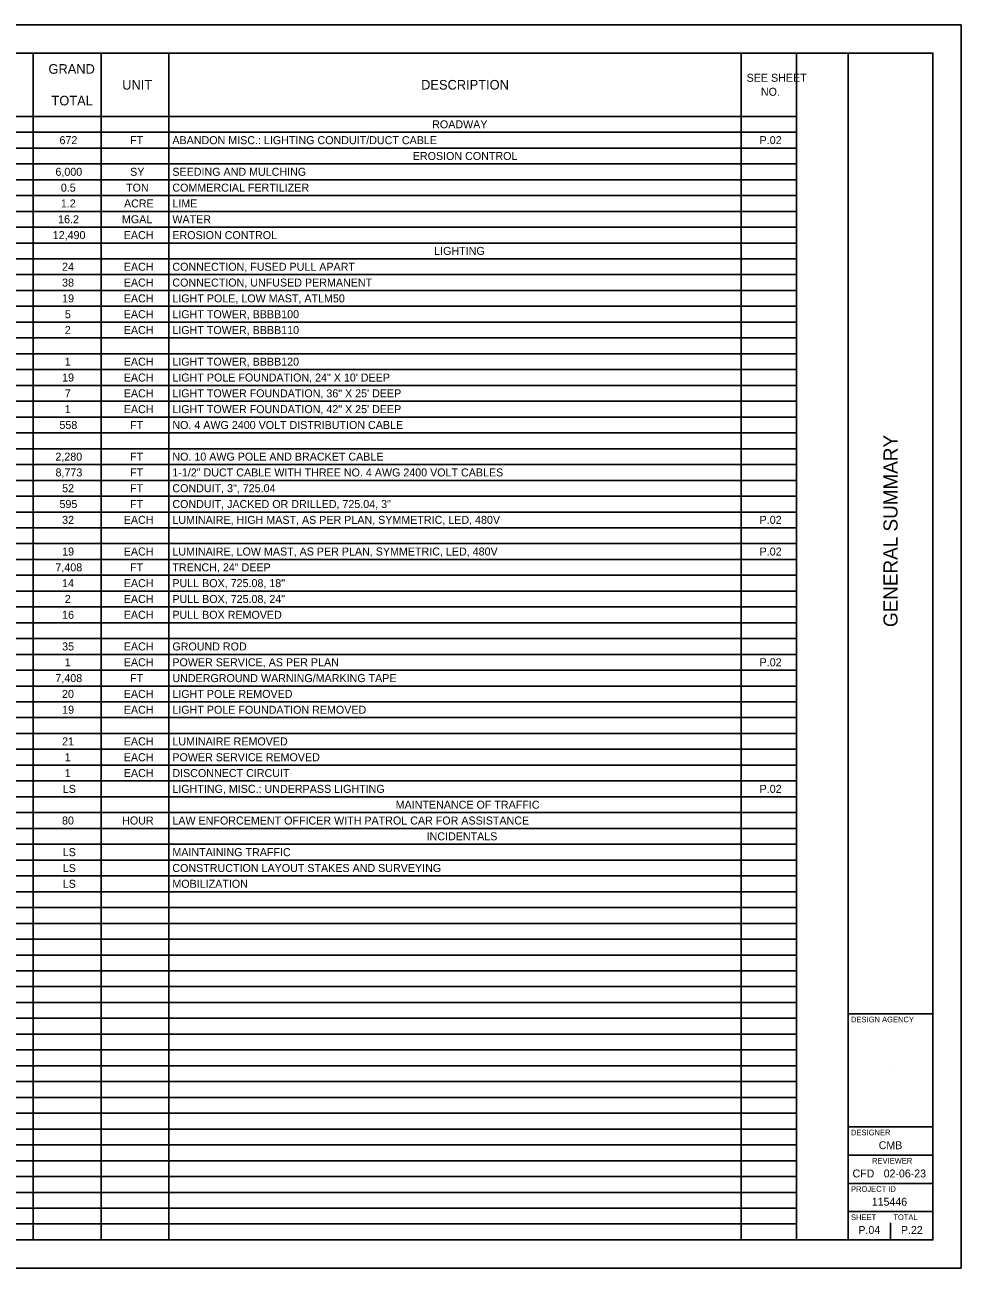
# Model space of a CAD drawing. Extents: x 0 to 34, y 0 to 22.
# Drawn here: x 17.43 to 34, y 0 to 22 of the extents above; entities that cross this region are included whole.
import ezdxf

# ---------------------------------------------------------------- set-up
doc = ezdxf.new("R2010")
doc.units = 0
for name, color, linetype in [('Default', 7, 'Continuous'), ('SH_Border', 7, 'Continuous'), ('SH_Cut_Line', 7, 'Continuous'), ('SH_Data', 7, 'Continuous')]:
    doc.layers.add(name, color=color, linetype=linetype)

msp = doc.modelspace()

# ---------------------------------------------------------------- linework, layer by layer
at = {"layer": 'Default'}
for p, q in [((13.224, 21.5), (31.083, 21.5)), ((17.578, 21.5), (17.578, 21.22)), ((18.777, 21.5), (18.777, 21.22)), ((19.977, 21.5), (19.977, 21.22)), ((30.106, 21.5), (30.106, 21.22)), ((31.083, 21.5), (31.083, 21.22)), ((17.578, 21.22), (17.578, 20.94)), ((18.777, 21.22), (18.777, 20.94)), ((19.977, 21.22), (19.977, 20.94)), ((30.106, 21.22), (30.106, 20.94)), ((31.083, 21.22), (31.083, 20.94)), ((17.578, 20.94), (17.578, 20.66)), ((18.777, 20.94), (18.777, 20.66)), ((19.977, 20.94), (19.977, 20.66)), ((30.106, 20.94), (30.106, 20.66)), ((31.083, 20.94), (31.083, 20.66)), ((17.578, 20.66), (17.578, 20.38)), ((18.777, 20.66), (18.777, 20.38)), ((19.977, 20.66), (19.977, 20.38)), ((30.106, 20.66), (30.106, 20.38)), ((31.083, 20.66), (31.083, 20.38)), ((13.224, 20.38), (31.083, 20.38)), ((17.578, 20.38), (17.578, 20.1)), ((18.777, 20.38), (18.777, 20.1)), ((19.977, 20.38), (19.977, 20.1)), ((30.106, 20.38), (30.106, 20.1)), ((31.083, 20.38), (31.083, 20.1)), ((13.224, 20.1), (31.083, 20.1)), ((17.578, 20.1), (17.578, 18.7)), ((18.777, 20.1), (18.777, 18.7)), ((19.977, 20.1), (19.977, 18.7)), ((30.106, 20.1), (30.106, 18.7)), ((31.083, 20.1), (31.083, 18.7)), ((13.224, 19.82), (31.083, 19.82)), ((13.224, 19.54), (31.083, 19.54)), ((13.224, 19.26), (31.083, 19.26)), ((13.224, 18.98), (31.083, 18.98)), ((13.224, 18.7), (31.083, 18.7)), ((17.578, 18.7), (17.578, 18.14)), ((18.777, 18.7), (18.777, 18.14)), ((19.977, 18.7), (19.977, 18.14)), ((30.106, 18.7), (30.106, 18.14)), ((31.083, 18.7), (31.083, 18.14)), ((13.224, 18.42), (31.083, 18.42)), ((13.224, 18.14), (31.083, 18.14)), ((17.578, 18.14), (17.578, 17.86)), ((18.777, 18.14), (18.777, 17.86)), ((19.977, 18.14), (19.977, 17.86)), ((30.106, 18.14), (30.106, 17.86)), ((31.083, 18.14), (31.083, 17.86)), ((13.224, 17.86), (31.083, 17.86)), ((17.578, 17.86), (17.578, 17.58)), ((18.777, 17.86), (18.777, 17.58)), ((19.977, 17.86), (19.977, 17.58)), ((30.106, 17.86), (30.106, 17.58)), ((31.083, 17.86), (31.083, 17.58)), ((13.224, 17.58), (31.083, 17.58)), ((17.578, 17.58), (17.578, 17.3)), ((18.777, 17.58), (18.777, 17.3)), ((19.977, 17.58), (19.977, 17.3)), ((30.106, 17.58), (30.106, 17.3)), ((31.083, 17.58), (31.083, 17.3)), ((13.224, 17.3), (31.083, 17.3)), ((17.578, 17.3), (17.578, 17.02)), ((18.777, 17.3), (18.777, 17.02)), ((19.977, 17.3), (19.977, 17.02)), ((30.106, 17.3), (30.106, 17.02)), ((31.083, 17.3), (31.083, 17.02)), ((13.224, 17.02), (31.083, 17.02)), ((17.578, 17.02), (17.578, 16.74)), ((18.777, 17.02), (18.777, 16.74)), ((19.977, 17.02), (19.977, 16.74)), ((30.106, 17.02), (30.106, 16.74)), ((31.083, 17.02), (31.083, 16.74)), ((13.224, 16.74), (31.083, 16.74)), ((17.578, 16.74), (17.578, 16.18)), ((18.777, 16.74), (18.777, 16.18)), ((19.977, 16.74), (19.977, 16.18)), ((30.106, 16.74), (30.106, 16.18)), ((31.083, 16.74), (31.083, 16.18)), ((13.224, 16.46), (31.083, 16.46)), ((13.224, 16.18), (31.083, 16.18)), ((17.578, 16.18), (17.578, 15.9)), ((18.777, 16.18), (18.777, 15.9)), ((19.977, 16.18), (19.977, 15.9)), ((30.106, 16.18), (30.106, 15.9)), ((31.083, 16.18), (31.083, 15.9)), ((13.224, 15.9), (31.083, 15.9)), ((17.578, 15.9), (17.578, 15.62)), ((18.777, 15.9), (18.777, 15.62)), ((19.977, 15.9), (19.977, 15.62)), ((30.106, 15.9), (30.106, 15.62)), ((31.083, 15.9), (31.083, 15.62)), ((13.224, 15.62), (31.083, 15.62)), ((17.578, 15.62), (17.578, 15.34)), ((18.777, 15.62), (18.777, 15.34)), ((19.977, 15.62), (19.977, 15.34)), ((30.106, 15.62), (30.106, 15.34)), ((31.083, 15.62), (31.083, 15.34)), ((13.224, 15.34), (31.083, 15.34)), ((17.578, 15.34), (17.578, 14.78)), ((18.777, 15.34), (18.777, 14.78)), ((19.977, 15.34), (19.977, 14.78)), ((30.106, 15.34), (30.106, 14.78)), ((31.083, 15.34), (31.083, 14.78)), ((13.224, 15.06), (31.083, 15.06)), ((13.224, 14.78), (31.083, 14.78)), ((17.578, 14.78), (17.578, 14.5)), ((18.777, 14.78), (18.777, 14.5)), ((19.977, 14.78), (19.977, 14.5)), ((30.106, 14.78), (30.106, 14.5)), ((31.083, 14.78), (31.083, 14.5)), ((13.224, 14.5), (31.083, 14.5)), ((17.578, 14.5), (17.578, 14.22)), ((18.777, 14.5), (18.777, 14.22)), ((19.977, 14.5), (19.977, 14.22)), ((30.106, 14.5), (30.106, 14.22)), ((31.083, 14.5), (31.083, 14.22)), ((13.224, 14.22), (31.083, 14.22)), ((17.578, 14.22), (17.578, 13.94)), ((18.777, 14.22), (18.777, 13.94)), ((19.977, 14.22), (19.977, 13.94)), ((30.106, 14.22), (30.106, 13.94)), ((31.083, 14.22), (31.083, 13.94)), ((13.224, 13.94), (31.083, 13.94)), ((17.578, 13.94), (17.578, 11.7)), ((18.777, 13.94), (18.777, 11.7)), ((19.977, 13.94), (19.977, 11.7)), ((30.106, 13.94), (30.106, 11.7)), ((31.083, 13.94), (31.083, 11.7)), ((13.224, 13.66), (31.083, 13.66)), ((13.224, 13.38), (31.083, 13.38)), ((13.224, 13.1), (31.083, 13.1)), ((13.224, 12.82), (31.083, 12.82)), ((13.224, 12.54), (31.083, 12.54)), ((13.224, 12.26), (31.083, 12.26)), ((13.224, 11.98), (31.083, 11.98)), ((13.224, 11.7), (31.083, 11.7)), ((17.578, 11.7), (17.578, 11.42)), ((18.777, 11.7), (18.777, 11.42)), ((19.977, 11.7), (19.977, 11.42)), ((30.106, 11.7), (30.106, 11.42)), ((31.083, 11.7), (31.083, 11.42)), ((13.224, 11.42), (31.083, 11.42)), ((17.578, 11.42), (17.578, 10.3)), ((18.777, 11.42), (18.777, 10.3)), ((19.977, 11.42), (19.977, 10.3)), ((30.106, 11.42), (30.106, 10.3)), ((31.083, 11.42), (31.083, 10.3)), ((13.224, 11.14), (31.083, 11.14)), ((13.224, 10.86), (31.083, 10.86)), ((13.224, 10.58), (31.083, 10.58)), ((13.224, 10.3), (31.083, 10.3)), ((17.578, 10.3), (17.578, 10.02)), ((18.777, 10.3), (18.777, 10.02)), ((19.977, 10.3), (19.977, 10.02)), ((30.106, 10.3), (30.106, 10.02)), ((31.083, 10.3), (31.083, 10.02)), ((13.224, 10.02), (31.083, 10.02)), ((17.578, 10.02), (17.578, 9.741)), ((18.777, 10.02), (18.777, 9.741)), ((19.977, 10.02), (19.977, 9.741)), ((30.106, 10.02), (30.106, 9.741)), ((31.083, 10.02), (31.083, 9.741)), ((13.224, 9.741), (31.083, 9.741)), ((17.578, 9.741), (17.578, 8.901)), ((18.777, 9.741), (18.777, 8.901)), ((19.977, 9.741), (19.977, 8.901)), ((30.106, 9.741), (30.106, 8.901)), ((31.083, 9.741), (31.083, 8.901)), ((13.224, 9.461), (31.083, 9.461)), ((13.224, 9.181), (31.083, 9.181)), ((13.224, 8.901), (31.083, 8.901)), ((17.578, 8.901), (17.578, 8.341)), ((18.777, 8.901), (18.777, 8.341)), ((19.977, 8.901), (19.977, 8.341)), ((30.106, 8.901), (30.106, 8.341)), ((31.083, 8.901), (31.083, 8.341)), ((13.224, 8.621), (31.083, 8.621)), ((13.224, 8.341), (31.083, 8.341)), ((17.578, 8.341), (17.578, 7.501)), ((18.777, 8.341), (18.777, 7.501)), ((19.977, 8.341), (19.977, 7.501)), ((30.106, 8.341), (30.106, 7.501)), ((31.083, 8.341), (31.083, 7.501)), ((13.224, 8.061), (31.083, 8.061)), ((13.224, 7.781), (31.083, 7.781)), ((13.224, 7.501), (31.083, 7.501)), ((17.578, 7.501), (17.578, 6.941)), ((18.777, 7.501), (18.777, 6.941)), ((19.977, 7.501), (19.977, 6.941)), ((30.106, 7.501), (30.106, 6.941)), ((31.083, 7.501), (31.083, 6.941)), ((13.224, 7.221), (31.083, 7.221)), ((13.224, 6.941), (31.083, 6.941)), ((17.578, 6.941), (17.578, 6.101)), ((18.777, 6.941), (18.777, 6.101)), ((19.977, 6.941), (19.977, 6.101)), ((30.106, 6.941), (30.106, 6.101)), ((31.083, 6.941), (31.083, 6.101)), ((13.224, 6.661), (31.083, 6.661)), ((13.224, 6.381), (31.083, 6.381)), ((13.224, 6.101), (31.083, 6.101)), ((17.578, 6.101), (17.578, 4.981)), ((18.777, 6.101), (18.777, 4.981)), ((19.977, 6.101), (19.977, 4.981)), ((30.106, 6.101), (30.106, 4.981)), ((31.083, 6.101), (31.083, 4.981)), ((13.224, 5.821), (31.083, 5.821)), ((13.224, 5.541), (31.083, 5.541)), ((13.224, 5.261), (31.083, 5.261)), ((13.224, 4.981), (31.083, 4.981)), ((17.578, 4.981), (17.578, 4.701)), ((18.777, 4.981), (18.777, 4.701)), ((19.977, 4.981), (19.977, 4.701)), ((30.106, 4.981), (30.106, 4.701)), ((31.083, 4.981), (31.083, 4.701)), ((13.224, 4.701), (31.083, 4.701)), ((17.578, 4.701), (17.578, 3.581)), ((18.777, 4.701), (18.777, 3.581)), ((19.977, 4.701), (19.977, 3.581)), ((30.106, 4.701), (30.106, 3.581)), ((31.083, 4.701), (31.083, 3.581)), ((13.224, 4.421), (31.083, 4.421)), ((13.224, 4.141), (31.083, 4.141)), ((13.224, 3.861), (31.083, 3.861)), ((13.224, 3.581), (31.083, 3.581)), ((17.578, 3.581), (17.578, 3.301)), ((18.777, 3.581), (18.777, 3.301)), ((19.977, 3.581), (19.977, 3.301)), ((30.106, 3.581), (30.106, 3.301)), ((31.083, 3.581), (31.083, 3.301)), ((13.224, 3.301), (31.083, 3.301)), ((17.578, 3.301), (17.578, 2.181)), ((18.777, 3.301), (18.777, 2.181)), ((19.977, 3.301), (19.977, 2.181)), ((30.106, 3.301), (30.106, 2.181)), ((31.083, 3.301), (31.083, 2.181)), ((13.224, 3.021), (31.083, 3.021)), ((13.224, 2.741), (31.083, 2.741)), ((13.224, 2.461), (31.083, 2.461)), ((13.224, 2.181), (31.083, 2.181)), ((17.578, 2.181), (17.578, 1.901)), ((18.777, 2.181), (18.777, 1.901)), ((19.977, 2.181), (19.977, 1.901)), ((30.106, 2.181), (30.106, 1.901)), ((31.083, 2.181), (31.083, 1.901)), ((13.224, 1.901), (31.083, 1.901)), ((17.578, 1.901), (17.578, 0.781)), ((18.777, 1.901), (18.777, 0.781)), ((19.977, 1.901), (19.977, 0.781)), ((30.106, 1.901), (30.106, 0.781)), ((31.083, 1.901), (31.083, 0.781)), ((13.224, 1.621), (31.083, 1.621)), ((13.224, 1.341), (31.083, 1.341)), ((13.224, 1.061), (31.083, 1.061)), ((13.224, 0.781), (31.083, 0.781)), ((17.578, 0.781), (17.578, 0.501)), ((18.777, 0.781), (18.777, 0.501)), ((19.977, 0.781), (19.977, 0.501)), ((30.106, 0.781), (30.106, 0.501)), ((31.083, 0.781), (31.083, 0.501)), ((13.224, 0.501), (31.083, 0.501))]:
    msp.add_line(p, q, dxfattribs=at)
at = {"layer": 'SH_Border'}
for p, q in [((32, 0.5), (32, 21.5)), ((32, 4.5), (33.5, 4.5)), ((32, 2.5), (33.5, 2.5)), ((32, 2), (33.5, 2)), ((32, 1.5), (33.5, 1.5)), ((32, 1), (33.5, 1))]:
    msp.add_line(p, q, dxfattribs=at)
msp.add_lwpolyline([(1.5, 21.5), (33.5, 21.5), (33.5, 0.5), (1.5, 0.5)], close=True, dxfattribs=at)
at = {"layer": 'SH_Cut_Line'}
msp.add_lwpolyline([(0, 0), (34, 0), (34, 22), (0, 22)], close=True, dxfattribs=at)
at = {"layer": 'SH_Data'}
for p, q in [((32.75, 3.5), (32.75, 3.5)), ((32.375, 0.675), (32.375, 0.675)), ((32.75, 0.5), (32.75, 0.8))]:
    msp.add_line(p, q, dxfattribs=at)

# ---------------------------------------------------------------- texts
at = {"layer": 'Default'}
for s, height, p in [('GRAND', 0.17, (17.846, 21.135)), ('SEE SHEET ', 0.1417, (30.203, 20.993)), ('UNIT', 0.17, (19.151, 20.855)), ('DESCRIPTION', 0.16999, (24.442, 20.855)), ('TOTAL', 0.17, (17.899, 20.575)), ('NO.', 0.1417, (30.456, 20.745)), ('ROADWAY', 0.1417, (24.637, 20.169)), ('672', 0.1417, (18.041, 19.889)), ('FT', 0.1417, (19.29, 19.889)), ('ABANDON MISC.: LIGHTING CONDUIT/DUCT CABLE', 0.14166, (20.039, 19.889)), ('P.02', 0.1417, (30.433, 19.889)), ('EROSION CONTROL', 0.14166, (24.294, 19.609)), ('6,000', 0.1417, (17.969, 19.329)), ('SY', 0.1417, (19.291, 19.329)), ('SEEDING AND MULCHING', 0.14166, (20.039, 19.329)), ('0.5', 0.1417, (18.065, 19.049)), ('TON', 0.1417, (19.22, 19.049)), ('COMMERCIAL FERTILIZER', 0.14166, (20.039, 19.049)), ('1.2', 0.1417, (18.065, 18.769)), ('ACRE', 0.1417, (19.183, 18.769)), ('LIME', 0.1417, (20.039, 18.769)), ('16.2', 0.1417, (18.017, 18.489)), ('MGAL', 0.1417, (19.146, 18.489)), ('WATER', 0.1417, (20.039, 18.489)), ('12,490', 0.1417, (17.921, 18.209)), ('EACH', 0.1417, (19.179, 18.209)), ('EROSION CONTROL', 0.14166, (20.039, 18.209)), ('LIGHTING', 0.1417, (24.673, 17.929)), ('24', 0.1417, (18.086, 17.649)), ('EACH', 0.1417, (19.179, 17.649)), ('CONNECTION, FUSED PULL APART', 0.14166, (20.039, 17.649)), ('38', 0.1417, (18.087, 17.369)), ('EACH', 0.1417, (19.179, 17.369)), ('CONNECTION, UNFUSED PERMANENT', 0.14166, (20.039, 17.369)), ('19', 0.1417, (18.088, 17.089)), ('EACH', 0.1417, (19.179, 17.089)), ('LIGHT POLE, LOW MAST, ATLM50', 0.14166, (20.039, 17.089)), ('5', 0.142, (18.136, 16.809)), ('EACH', 0.1417, (19.179, 16.809)), ('LIGHT TOWER, BBBB100', 0.14166, (20.039, 16.809)), ('2', 0.142, (18.135, 16.529)), ('EACH', 0.1417, (19.179, 16.529)), ('LIGHT TOWER, BBBB110', 0.14166, (20.039, 16.529)), ('1', 0.142, (18.135, 15.969)), ('EACH', 0.1417, (19.179, 15.969)), ('LIGHT TOWER, BBBB120', 0.14166, (20.039, 15.969)), ('19', 0.1417, (18.088, 15.689)), ('EACH', 0.1417, (19.179, 15.689)), ('LIGHT POLE FOUNDATION, 24" X 10\' DEEP', 0.14166, (20.039, 15.689)), ('7', 0.142, (18.135, 15.409)), ('EACH', 0.1417, (19.179, 15.409)), ('LIGHT TOWER FOUNDATION, 36" X 25\' DEEP', 0.14166, (20.039, 15.409)), ('1', 0.142, (18.135, 15.129)), ('EACH', 0.1417, (19.179, 15.129)), ('LIGHT TOWER FOUNDATION, 42" X 25\' DEEP', 0.14166, (20.039, 15.129)), ('558', 0.1417, (18.04, 14.849)), ('FT', 0.1417, (19.29, 14.849)), ('NO. 4 AWG 2400 VOLT DISTRIBUTION CABLE', 0.14166, (20.039, 14.849)), ('2,280', 0.1417, (17.969, 14.289)), ('FT', 0.1417, (19.29, 14.289)), ('NO. 10 AWG POLE AND BRACKET CABLE', 0.14166, (20.039, 14.289)), ('8,773', 0.1417, (17.971, 14.009)), ('FT', 0.1417, (19.29, 14.009)), ('1-1/2" DUCT CABLE WITH THREE NO. 4 AWG 2400 VOLT CABLES', 0.14166, (20.039, 14.009)), ('52', 0.1417, (18.088, 13.73)), ('FT', 0.1417, (19.29, 13.73)), ('CONDUIT, 3", 725.04', 0.14166, (20.039, 13.73)), ('595', 0.1417, (18.041, 13.45)), ('FT', 0.1417, (19.29, 13.45)), ('CONDUIT, JACKED OR DRILLED, 725.04, 3"', 0.14166, (20.039, 13.45)), ('32', 0.1417, (18.088, 13.17)), ('EACH', 0.1417, (19.179, 13.17)), ('LUMINAIRE, HIGH MAST, AS PER PLAN, SYMMETRIC, LED, 480V', 0.14166, (20.039, 13.17)), ('P.02', 0.1417, (30.433, 13.17)), ('19', 0.1417, (18.088, 12.61)), ('EACH', 0.1417, (19.179, 12.61)), ('LUMINAIRE, LOW MAST, AS PER PLAN, SYMMETRIC, LED, 480V', 0.14166, (20.039, 12.61)), ('P.02', 0.1417, (30.433, 12.61)), ('7,408', 0.1417, (17.969, 12.33)), ('FT', 0.1417, (19.29, 12.33)), ('TRENCH, 24" DEEP', 0.14166, (20.039, 12.33)), ('14', 0.1417, (18.086, 12.05)), ('EACH', 0.1417, (19.179, 12.05)), ('PULL BOX, 725.08, 18"', 0.14166, (20.039, 12.05)), ('2', 0.142, (18.135, 11.77)), ('EACH', 0.1417, (19.179, 11.77)), ('PULL BOX, 725.08, 24"', 0.14166, (20.039, 11.77)), ('16', 0.1417, (18.087, 11.49)), ('EACH', 0.1417, (19.179, 11.49)), ('PULL BOX REMOVED', 0.14166, (20.039, 11.49)), ('35', 0.1417, (18.088, 10.93)), ('EACH', 0.1417, (19.179, 10.93)), ('GROUND ROD', 0.1417, (20.039, 10.93)), ('1', 0.142, (18.135, 10.65)), ('EACH', 0.1417, (19.179, 10.65)), ('POWER SERVICE, AS PER PLAN', 0.14166, (20.039, 10.65)), ('P.02', 0.1417, (30.433, 10.65)), ('7,408', 0.1417, (17.969, 10.37)), ('FT', 0.1417, (19.29, 10.37)), ('UNDERGROUND WARNING/MARKING TAPE', 0.14166, (20.039, 10.37)), ('20', 0.1417, (18.086, 10.09)), ('EACH', 0.1417, (19.179, 10.09)), ('LIGHT POLE REMOVED', 0.14166, (20.039, 10.09)), ('19', 0.1417, (18.088, 9.81)), ('EACH', 0.1417, (19.179, 9.81)), ('LIGHT POLE FOUNDATION REMOVED', 0.14166, (20.039, 9.81)), ('21', 0.1417, (18.088, 9.25)), ('EACH', 0.1417, (19.179, 9.25)), ('LUMINAIRE REMOVED', 0.14166, (20.039, 9.25)), ('1', 0.142, (18.135, 8.97)), ('EACH', 0.1417, (19.179, 8.97)), ('POWER SERVICE REMOVED', 0.14166, (20.039, 8.97)), ('1', 0.142, (18.135, 8.69)), ('EACH', 0.1417, (19.179, 8.69)), ('DISCONNECT CIRCUIT', 0.14166, (20.039, 8.69)), ('LS', 0.1417, (18.099, 8.41)), ('LIGHTING, MISC.: UNDERPASS LIGHTING', 0.14166, (20.039, 8.41)), ('P.02', 0.1417, (30.433, 8.41)), ('MAINTENANCE OF TRAFFIC', 0.14166, (23.991, 8.13)), ('80', 0.1417, (18.086, 7.85)), ('HOUR', 0.1417, (19.15, 7.85)), ('LAW ENFORCEMENT OFFICER WITH PATROL CAR FOR ASSISTANCE', 0.14166, (20.039, 7.85)), ('INCIDENTALS', 0.14166, (24.539, 7.57)), ('LS', 0.1417, (18.099, 7.29)), ('MAINTAINING TRAFFIC', 0.14166, (20.039, 7.29)), ('LS', 0.1417, (18.099, 7.01)), ('CONSTRUCTION LAYOUT STAKES AND SURVEYING', 0.14166, (20.039, 7.01)), ('LS', 0.1417, (18.099, 6.73)), ('MOBILIZATION', 0.14166, (20.039, 6.73))]:
    msp.add_text(s, height=height, dxfattribs=at).set_placement(p)
at = {"layer": 'SH_Data'}
msp.add_text('GENERAL SUMMARY', height=0.25, rotation=90, dxfattribs=at).set_placement((32.875, 11.344))
for s, height, p in [('DESIGN AGENCY', 0.1, (32.05, 4.35)), ('DESIGNER', 0.1, (32.05, 2.35)), ('CMB', 0.14, (32.542, 2.105)), ('REVIEWER', 0.1, (32.422, 1.85)), ('CFD', 0.14, (32.078, 1.605)), ('02-06-23', 0.14, (32.629, 1.605)), ('PROJECT ID', 0.1, (32.05, 1.35)), ('115446', 0.14, (32.419, 1.105)), ('SHEET', 0.1, (32.05, 0.85)), ('TOTAL', 0.1, (32.8, 0.85)), ('P.04', 0.14, (32.182, 0.605)), ('P.22', 0.14, (32.935, 0.605))]:
    msp.add_text(s, height=height, dxfattribs=at).set_placement(p)

doc.saveas('drawing.dxf')
